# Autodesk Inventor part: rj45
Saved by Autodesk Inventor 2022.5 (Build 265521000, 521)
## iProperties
Created: 2024-12
Part Number: rj45
Material: Generic
Document SubType Name: Modeling
Designer: AdminForWorker
Density: 1 g/cm^3
Appearance: Default
Title: rj45
Author: AdminForWorker
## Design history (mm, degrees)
feature "Body1"
feature "Body2"
feature "Body3"
feature "Body4"
feature "Body5"
feature "Body6"
feature "Body7"
feature "Body8"
feature "Body9"
body "Solid1"
body "Solid2"
body "Solid3"
body "Solid4"
body "Solid5"
body "Solid6"
body "Solid7"
body "Solid8"
body "Solid9"
